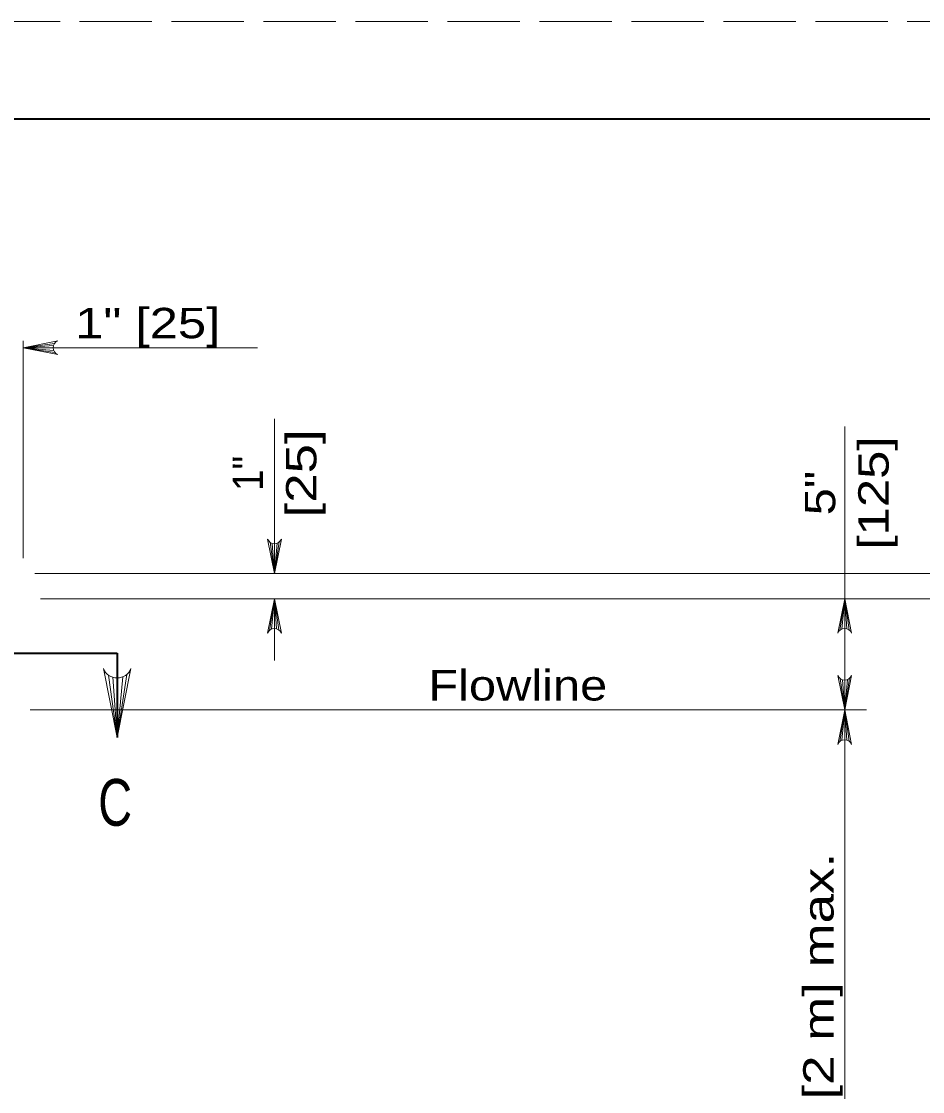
# Model space of a CAD drawing. Extents: x -410.5 to -376.5, y 1617.6 to 1661.6.
# Drawn here: x -400.72 to -396.1, y 1656.07 to 1661.56 of the extents above; entities that cross this region are included whole.
import ezdxf
from ezdxf.enums import TextEntityAlignment as Align

# ---------------------------------------------------------------- set-up
doc = ezdxf.new("R2010")
doc.units = 0
doc.header["$LTSCALE"] = 0.062
doc.linetypes.add('LONG_DASHED', pattern=[7.5, 6, -1.5])
doc.layers.add('1', color=7, linetype='Continuous', lineweight=13)

msp = doc.modelspace()

# ---------------------------------------------------------------- linework, layer by layer
at = {"layer": '1', "lineweight": 25}
msp.add_line((-408.45475, 1661.06183), (-376.95475, 1661.06183), dxfattribs=at)
at = {"layer": '1'}
for p, q in [((-400.71542, 1658.80683), (-400.71542, 1659.92217)), ((-400.55517, 1659.90942), (-400.71542, 1659.887)), ((-400.56058, 1659.89833), (-400.71542, 1659.887)), ((-400.56225, 1659.887), (-400.71542, 1659.887)), ((-400.55942, 1659.87258), (-400.71542, 1659.887)), ((-400.55333, 1659.86225), (-400.71542, 1659.887)), ((-400.71542, 1659.887), (-399.51283, 1659.887)), ((-399.42633, 1658.72817), (-399.42633, 1659.52175)), ((-396.50017, 1659.4835), (-396.50017, 1658.0285)), ((-399.44875, 1658.88842), (-399.42633, 1658.72817)), ((-399.43767, 1658.883), (-399.42633, 1658.72817)), ((-399.40158, 1658.89033), (-399.42633, 1658.72817)), ((-399.412, 1658.88417), (-399.42633, 1658.72817)), ((-399.42633, 1658.88133), (-399.42633, 1658.72817)), ((-400.65567, 1658.72817), (-394.85592, 1658.72817)), ((-400.62708, 1658.59883), (-394.85592, 1658.59883)), ((-399.45117, 1658.43658), (-399.42633, 1658.59875)), ((-399.44075, 1658.44275), (-399.42633, 1658.59875)), ((-399.42633, 1658.28133), (-399.42633, 1658.59883)), ((-399.42633, 1658.44558), (-399.42633, 1658.59875)), ((-399.415, 1658.44392), (-399.42633, 1658.59875)), ((-399.40392, 1658.4385), (-399.42633, 1658.59875)), ((-396.525, 1658.43675), (-396.50017, 1658.59883)), ((-396.51458, 1658.44292), (-396.50017, 1658.59883)), ((-396.50017, 1658.59883), (-396.50017, 1658.4455)), ((-396.50017, 1658.44575), (-396.50017, 1658.59883)), ((-396.48892, 1658.44408), (-396.50017, 1658.59883)), ((-396.47775, 1658.43867), (-396.50017, 1658.59883)), ((-400.27825, 1658.2065), (-400.23342, 1657.886)), ((-400.18383, 1658.21033), (-400.23342, 1657.886)), ((-400.20458, 1658.198), (-400.23342, 1657.886)), ((-400.25608, 1658.19567), (-400.23342, 1657.886)), ((-400.23342, 1658.19233), (-400.23342, 1657.886)), ((-396.52258, 1658.18875), (-396.50017, 1658.0285)), ((-396.5115, 1658.18333), (-396.50017, 1658.0285)), ((-396.47542, 1658.19067), (-396.50017, 1658.0285)), ((-396.48583, 1658.1845), (-396.50017, 1658.0285)), ((-396.50017, 1658.18367), (-396.50017, 1658.0285)), ((-396.50017, 1658.18167), (-396.50017, 1658.0285)), ((-400.67933, 1658.0285), (-396.38892, 1658.0285)), ((-396.525, 1657.86642), (-396.50017, 1658.0285)), ((-396.51458, 1657.8725), (-396.50017, 1658.0285)), ((-396.50017, 1657.87533), (-396.50017, 1658.0285)), ((-396.48892, 1657.87375), (-396.50017, 1658.0285)), ((-396.47775, 1657.86825), (-396.50017, 1658.0285)), ((-396.50017, 1658.02708), (-396.50017, 1655.1135))]:
    msp.add_line(p, q, dxfattribs=at)
at = {"layer": '1', "lineweight": 35}
for p, q in [((-405.89092, 1658.31867), (-400.23342, 1658.31867)), ((-400.23342, 1658.31867), (-400.23342, 1657.886))]:
    msp.add_line(p, q, dxfattribs=at)
at = {"layer": '1', "linetype": 'LONG_DASHED'}
msp.add_lwpolyline([(-410.45475, 1639.56183), (-376.45475, 1639.56183), (-376.45475, 1661.56183), (-410.45475, 1661.56183)], close=True, dxfattribs=at)
at = {"layer": '1', "lineweight": 40}
msp.add_lwpolyline([(-408.45475, 1661.06183), (-376.95475, 1661.06183), (-376.95475, 1640.06183), (-408.45475, 1640.06183)], close=True, dxfattribs=at)
msp.add_lwpolyline([(-408.45475, 1661.06183), (-376.95475, 1661.06183), (-376.95475, 1640.06183), (-408.45475, 1640.06183)], close=True, dxfattribs=at)
at = {"layer": '1'}
for points in [[(-400.53842, 1659.85158), (-400.71542, 1659.887), (-400.53842, 1659.92242)], [(-399.391, 1658.90517), (-399.42633, 1658.72817), (-399.46175, 1658.90517)], [(-399.46175, 1658.42175), (-399.42633, 1658.59875), (-399.391, 1658.42175)], [(-396.53558, 1658.42183), (-396.50017, 1658.59883), (-396.46483, 1658.42183)], [(-400.16258, 1658.24), (-400.23342, 1657.886), (-400.30417, 1658.24)], [(-396.46483, 1658.2055), (-396.50017, 1658.0285), (-396.53558, 1658.2055)], [(-396.53558, 1657.8515), (-396.50017, 1658.0285), (-396.46483, 1657.8515)]]:
    msp.add_lwpolyline(points, dxfattribs=at)
for centre, radius, start, end in [((-400.52413, 1659.88703), 0.0382, 112.08782, 247.91395), ((-399.4264, 1658.9195), 0.0382, 202.08782, 337.91395), ((-399.42632, 1658.40744), 0.0382, 22.08782, 157.91395), ((-396.50017, 1658.40758), 0.0382, 22.08782, 157.91395), ((-400.23347, 1658.26863), 0.0764, 202.08782, 337.91395), ((-396.50024, 1658.21983), 0.0382, 202.08782, 337.91395), ((-396.50017, 1657.83724), 0.0382, 22.08782, 157.91395)]:
    msp.add_arc(centre, radius, start, end, dxfattribs=at)

# ---------------------------------------------------------------- texts
for s, width, p in [('1" [25]', 1.25, (-400.44933, 1659.93567)), ('Flowline', 1.2, (-398.63692, 1658.0765))]:
    msp.add_text(s, height=0.156, dxfattribs=dict(at, width=width)).set_placement(p)
for s, width, p in [('[25]', 1.3, (-399.211, 1659.24212)), ('[125]', 1.25, (-396.27458, 1659.14125)), ('1"', 0.95, (-399.485, 1659.24212)), ('5"', 1.2, (-396.54858, 1659.14129)), ("Variable depth 6' [2 m] max.", 1.3, (-396.55708, 1655.61029))]:
    msp.add_text(s, height=0.156, rotation=90, dxfattribs=dict(at, width=width)).set_placement(p, align=Align.CENTER)
at = {"layer": '1', "width": 0.75}
msp.add_text('C', height=0.24, dxfattribs=at).set_placement((-400.24383, 1657.43358), align=Align.CENTER)

doc.saveas('drawing.dxf')
